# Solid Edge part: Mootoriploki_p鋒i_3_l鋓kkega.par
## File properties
Author: KULL
Template: Iso Metric Part.par
Last saved by: KULL
Revision: 21
Application: Solid Edge
Accuracy: 0,990
Face Style: Model Default
Fill Style: Normal
Coef. of Thermal Exp: 0.0
Thermal Conductivity: 0.0
Specific Heat: 0.0
Modulus of Elasticity: 0.0
Poisson's Ratio: 0.0
Yield Stress: 0.0
Ultimate Stress: 0.0
Elongation: 0.0
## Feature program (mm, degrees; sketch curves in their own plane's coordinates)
sketch for "Hole_1" plane through (0, 0, 2.6435) normal (0, 0, -1) x-axis (1, 0, 0)
hole "Hole_1" diameter 1.4 finite
sketch for "unnamed Hole 1" plane through (0, 0, 2.6435) normal (0, 0, -1) x-axis (1, 0, 0)
hole "unnamed Hole 1" finite
sketch for "unnamed Hole 2" plane through (0, 0, 2.6435) normal (0, 0, -1) x-axis (1, 0, 0)
  hole centre (0, 18.6197) bore radius 0.7
hole "unnamed Hole 2" finite
sketch for "unnamed Hole 3" plane through (0, 0, 2.6435) normal (0, 0, -1) x-axis (1, 0, 0)
  hole centre (-18, 18.6197) bore radius 0.7
hole "unnamed Hole 3" finite
sketch for "unnamed Hole 4" plane through (0, 0, 2.6435) normal (0, 0, -1) x-axis (1, 0, 0)
  hole centre (-33.7, 18.6197) bore radius 0.7
hole "unnamed Hole 4" finite
sketch for "unnamed Hole 5" plane through (0, 0, 2.6435) normal (0, 0, -1) x-axis (1, 0, 0)
  hole centre (33.7, -18.6197) bore radius 0.7
hole "unnamed Hole 5" finite
sketch for "unnamed Hole 6" plane through (0, 0, 2.6435) normal (0, 0, -1) x-axis (1, 0, 0)
  hole centre (18, -18.6197) bore radius 0.7
hole "unnamed Hole 6" finite
sketch for "unnamed Hole 7" plane through (0, 0, 2.6435) normal (0, 0, -1) x-axis (1, 0, 0)
  hole centre (0, -18.6197) bore radius 0.7
hole "unnamed Hole 7" finite
sketch for "unnamed Hole 8" plane through (0, 0, 2.6435) normal (0, 0, -1) x-axis (1, 0, 0)
  hole centre (-18, -18.6197) bore radius 0.7
hole "unnamed Hole 8" finite
sketch for "unnamed Hole 9" plane through (0, 0, 2.6435) normal (0, 0, -1) x-axis (1, 0, 0)
  hole centre (-33.7, -18.6197) bore radius 0.7
hole "unnamed Hole 9" finite
pattern "unnamed Pattern 1" of "Hole_1", "unnamed Hole 1", "unnamed Hole 2", "unnamed Hole 3", "unnamed Hole 4", "unnamed Hole 5", "unnamed Hole 6", "unnamed Hole 7", "unnamed Hole 8", "unnamed Hole 9"
sketch for "Hole_11" plane through (0, 0, 3.6435) normal (0, 0, -1) x-axis (1, 0, 0)
  hole centre (-45.4, 8.3485) bore radius 0.7
hole "Hole_11" diameter 1.4 finite
sketch for "unnamed Hole 10" plane through (0, 0, 3.6435) normal (0, 0, -1) x-axis (1, 0, 0)
  hole centre (-45.4, 0) bore radius 0.7
hole "unnamed Hole 10" finite
sketch for "unnamed Hole 11" plane through (0, 0, 3.6435) normal (0, 0, -1) x-axis (1, 0, 0)
  hole centre (45.4, 8.3485) bore radius 0.7
hole "unnamed Hole 11" finite
sketch for "unnamed Hole 12" plane through (0, 0, 3.6435) normal (0, 0, -1) x-axis (1, 0, 0)
  hole centre (45.4, 0) bore radius 0.7
hole "unnamed Hole 12" finite
sketch for "unnamed Hole 13" plane through (0, 0, 3.6435) normal (0, 0, -1) x-axis (1, 0, 0)
  hole centre (45.4, -8.3485) bore radius 0.7
hole "unnamed Hole 13" finite
sketch for "unnamed Hole 14" plane through (0, 0, 3.6435) normal (0, 0, -1) x-axis (1, 0, 0)
  hole centre (-45.4, -8.3485) bore radius 0.7
hole "unnamed Hole 14" finite
pattern "unnamed Pattern 2" of "Hole_11", "unnamed Hole 10", "unnamed Hole 11", "unnamed Hole 12", "unnamed Hole 13", "unnamed Hole 14"
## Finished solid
Body 1: solid body, 274 faces, 640 edges, 364 vertices.
  Faces by surface: cylinder 110, plane 64, blend 62, torus 28, sphere 6, swept 4
  Edges by curve: line 228, circle 224, intersection 108, ellipse 76, spline 4
Bounding box of the edges (mm; curved faces can reach further): 102.794 x 41.218 x 13.316, from (-51.3987, -20.6087, 2.6435) to (51.3957, 20.6087, 15.959).
Cylindrical faces by radius (mm): R0.05 x14, R0.1 x22, R0.2 x8, R0.7 x16, R1.4 x6, R1.8 x10, R3 x18, R4 x4, R6 x4, R8 x6, R9.5 x2
Toroidal faces (ring radius, tube radius in mm): R1.5875 r0.2 x6, R1.75 r0.05 x10, R7.8 r0.2 x2, R7.9 r0.1 x4, R8.2 r0.2 x2, R9.3 r0.2 x2, R11.5 r2 x2
Spherical faces by radius (mm): R1.4 x6
Planar faces by outward normal: +x 9, +y 1, +z 12, -x 9, -y 1, -z 18, oblique 14
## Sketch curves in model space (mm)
spline (-47, 10.5199, 2.6435) -> (-44.9475, 15.5468, 2.6435) -> (-40, 17.6197, 2.6435)
line (-47, -10.5199, 2.6435) -> (-47, 10.5199, 2.6435)
spline (-40, -17.6197, 2.6435) -> (-44.9475, -15.5468, 2.6435) -> (-47, -10.5199, 2.6435)
spline (47, -10.5199, 2.6435) -> (44.9475, -15.5468, 2.6435) -> (40, -17.6197, 2.6435)
line (47, 10.5199, 2.6435) -> (47, -10.5199, 2.6435)
spline (40, 17.6197, 2.6435) -> (44.9475, 15.5468, 2.6435) -> (47, 10.5199, 2.6435)
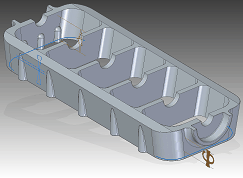
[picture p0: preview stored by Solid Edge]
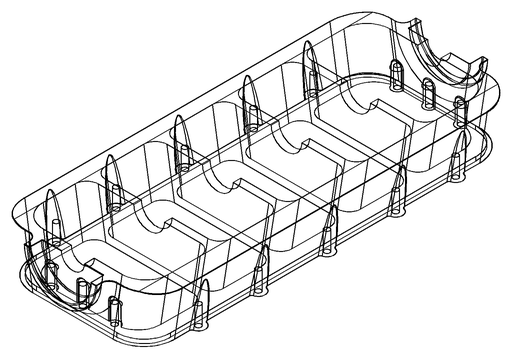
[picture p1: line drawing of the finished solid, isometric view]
